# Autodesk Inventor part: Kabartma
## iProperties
Created: 2009-12
Part Number: Kabartma
Document SubType Name: Modeling
Designer: bulent
Density: 1 g/cm^3
Author: bulent
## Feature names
1. Extrusion1
